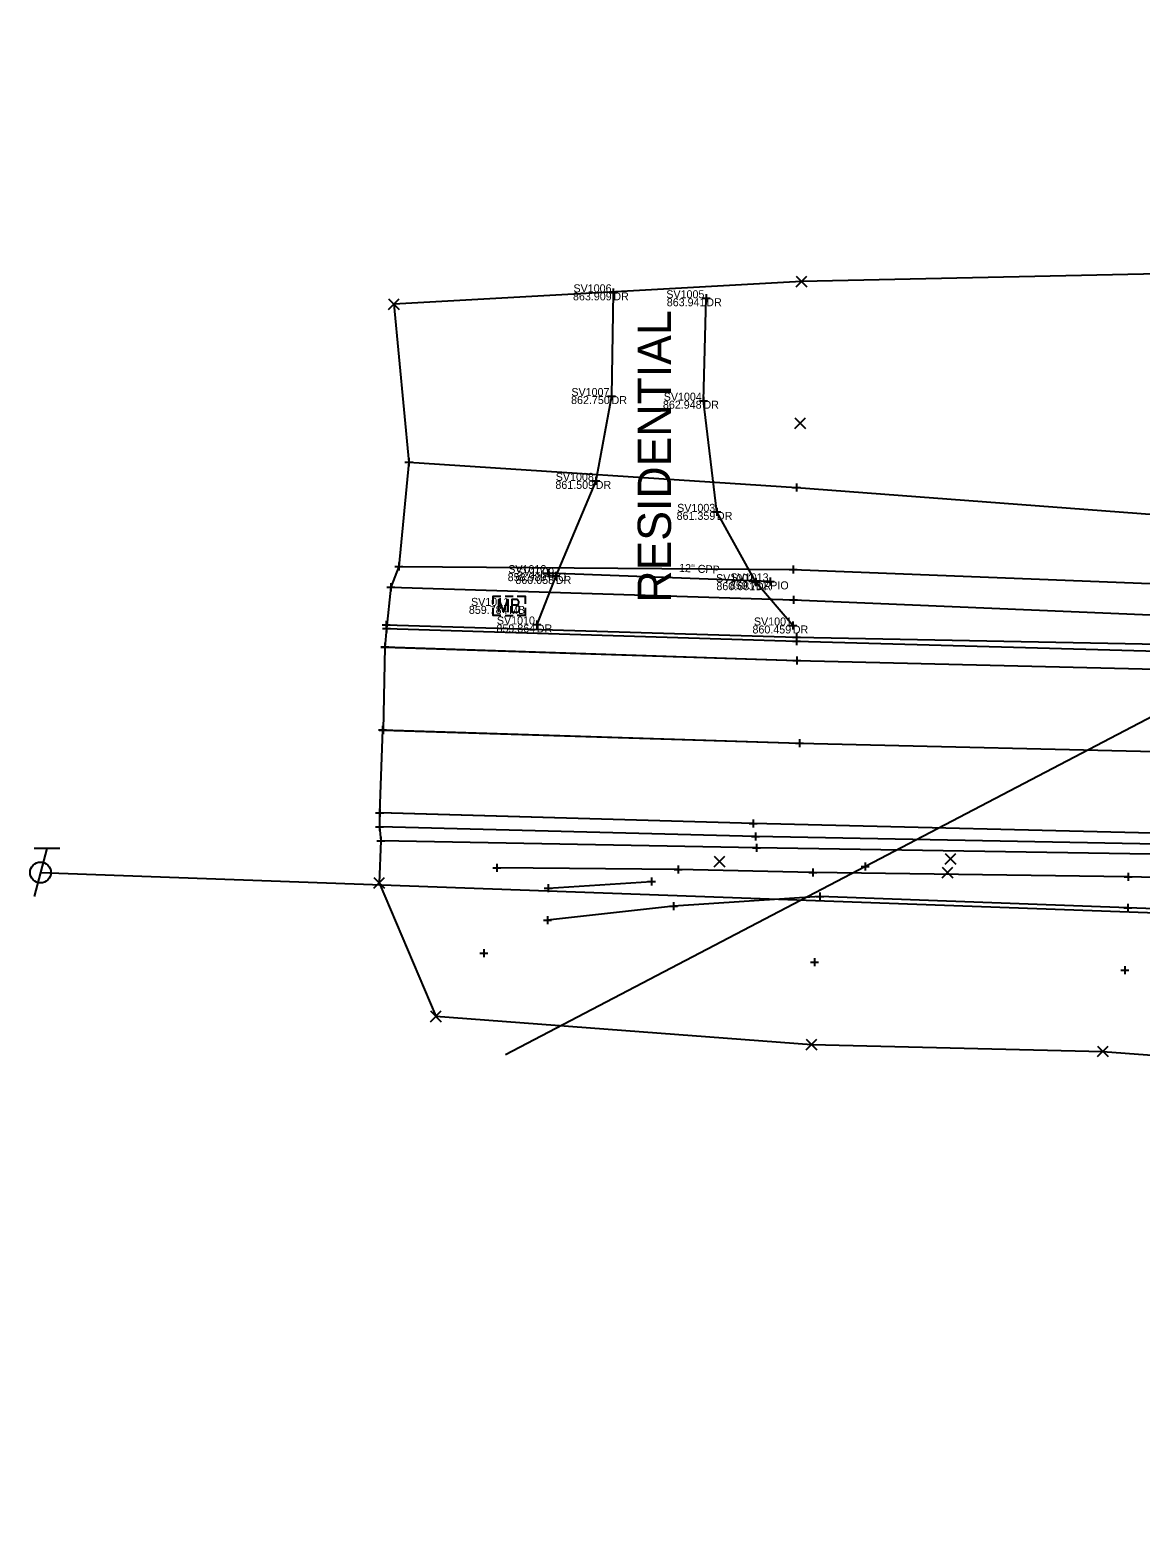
# Model space of a CAD drawing. Extents: x 2005176 to 2005823, y 572472 to 572942.
# Drawn here: x 2005176.4 to 2005315.2, y 572515.6 to 572703.5 of the extents above; entities that cross this region are included whole.
import ezdxf

# ---------------------------------------------------------------- set-up
doc = ezdxf.new("R2010")
doc.units = 0
for name, color, linetype in [('_CIVIL_CONSTRUCTION', 7, 'Continuous'), ('DR_X_Storm_Sewer', 7, 'Continuous'), ('DR_X_Text', 7, 'Continuous'), ('DV_X_Property_Line', 7, 'Continuous'), ('GE_X_Alignment_100_Bearings', 7, 'Continuous'), ('GE_X_Alignment_100_Cardinal_Points', 7, 'Continuous'), ('GE_X_Alignment_100_Curve_Data', 7, 'Continuous'), ('GE_X_Alignment_100_Distances', 7, 'Continuous'), ('GE_X_Alignment_100_Stations', 7, 'Continuous'), ('GE_X_Alignment_500_Bearings', 7, 'Continuous'), ('GE_X_Alignment_500_Cardinal_Points', 7, 'Continuous'), ('GE_X_Alignment_500_Distances', 7, 'Continuous'), ('PV_X_COP', 7, 'Continuous'), ('SC_Scratch1', 7, 'Continuous'), ('SC_Scratch10', 7, 'Continuous'), ('SC_Scratch8', 7, 'Continuous'), ('SV_P_Mon_Cells_Set', 7, 'Continuous'), ('SV_X_Control_Cells_Found', 7, 'Continuous'), ('SV_X_Mon_Cells_Found', 7, 'Continuous'), ('SV_X_Random_Point', 7, 'Continuous'), ('SV_X_Terrain_Boundary', 7, 'Continuous'), ('UT_X_Overhead_Electric', 7, 'Continuous'), ('UT_X_Overhead_Telecom', 7, 'Continuous')]:
    doc.layers.add(name, color=color, linetype=linetype)

msp = doc.modelspace()

# ---------------------------------------------------------------- linework, layer by layer
at = {"layer": '_CIVIL_CONSTRUCTION'}
for p, q in [((2005240.59, 572635.62), (2005241.59, 572635.62)), ((2005241.09, 572636.12), (2005241.09, 572635.12)), ((2005241.09, 572635.62), (2005241.09, 572635.62)), ((2005268.86, 572635.09), (2005268.86, 572634.09)), ((2005268.36, 572634.59), (2005269.36, 572634.59)), ((2005268.86, 572634.59), (2005268.86, 572634.59))]:
    msp.add_line(p, q, dxfattribs=at)
at = {"layer": 'DR_X_Storm_Sewer'}
msp.add_line((2005268.86, 572634.59), (2005241.09, 572635.62), dxfattribs=at)
at = {"layer": 'GE_X_Alignment_100_Bearings'}
for points in [[(2005220.7, 572626.42), (2005272.19, 572624.71), (2005322.24, 572623.5), (2005370.59, 572622.7), (2005425.14, 572621.65), (2005477.36, 572620.84), (2005525.07, 572619.6), (2005576.7, 572617.86), (2005628.14, 572615.99), (2005678.39, 572614.09), (2005728.23, 572612.03), (2005777.04, 572611.02), (2005819.95, 572609.99)], [(2005818.64, 572588.97), (2005775.2, 572590.4), (2005728.29, 572591.88), (2005676.68, 572593.61), (2005626.55, 572595.19), (2005577.83, 572596.72), (2005526.97, 572598.44), (2005477.01, 572599.53), (2005423.67, 572600.7), (2005368.75, 572601.99), (2005321.74, 572602.99), (2005266.72, 572604.35), (2005220.03, 572605.66)]]:
    msp.add_lwpolyline(points, dxfattribs=at)
at = {"layer": 'GE_X_Alignment_100_Cardinal_Points'}
msp.add_lwpolyline([(2005220.5, 572615.99), (2005272.51, 572614.37), (2005322.2, 572613.2), (2005370.62, 572612.29), (2005424.94, 572611.27), (2005476.5, 572610.17), (2005524.32, 572608.79), (2005576.49, 572607.4), (2005627.69, 572605.77), (2005677.11, 572603.68), (2005728.03, 572601.92), (2005776.18, 572600.5), (2005820.14, 572599.28)], dxfattribs=at)
at = {"layer": 'GE_X_Alignment_100_Curve_Data'}
for points in [[(2005249.25, 572670.71), (2005249.03, 572657.75), (2005247.05, 572647.15), (2005242.07, 572635.27), (2005239.68, 572629.21)], [(2005271.68, 572629.08), (2005267.07, 572634.49), (2005262.2, 572643.28), (2005260.51, 572657.17), (2005260.87, 572669.97)]]:
    msp.add_lwpolyline(points, dxfattribs=at)
at = {"layer": 'GE_X_Alignment_100_Distances'}
for points in [[(2005220.68, 572626.38), (2005272.19, 572624.71), (2005322.24, 572623.5), (2005370.59, 572622.7), (2005425.14, 572621.65), (2005477.36, 572620.84), (2005525.07, 572619.6), (2005576.7, 572617.86), (2005628.14, 572615.99), (2005678.39, 572614.09), (2005728.23, 572612.03), (2005777.04, 572611.02), (2005820.02, 572609.9)], [(2005818.7, 572589.05), (2005775.2, 572590.4), (2005728.29, 572591.88), (2005676.68, 572593.61), (2005626.55, 572595.19), (2005577.83, 572596.72), (2005526.97, 572598.44), (2005477.01, 572599.53), (2005423.67, 572600.7), (2005368.75, 572601.99), (2005321.74, 572602.99), (2005266.72, 572604.35), (2005220.06, 572605.65)]]:
    msp.add_lwpolyline(points, dxfattribs=at)
at = {"layer": 'GE_X_Alignment_100_Stations'}
for points in [[(2005222.43, 572636.47), (2005271.73, 572636.06), (2005321.63, 572634.11), (2005368.05, 572633.72), (2005426.44, 572630.35), (2005456.6, 572629.27), (2005476.49, 572629.52), (2005493.02, 572629.48), (2005502.46, 572637.33)], [(2005435.44, 572594.97), (2005419.01, 572594.84), (2005363.8, 572596.44), (2005313.6, 572597.65), (2005274.17, 572598.2), (2005257.36, 572598.58), (2005234.71, 572598.81)]]:
    msp.add_lwpolyline(points, dxfattribs=at)
at = {"layer": 'GE_X_Alignment_500_Bearings'}
for points in [[(2005221.46, 572633.88), (2005271.77, 572632.29), (2005321.33, 572630.21), (2005368.11, 572629.36), (2005426.58, 572628.14), (2005455.88, 572627.02), (2005475.7, 572627.77)], [(2005241.12, 572596.26), (2005254.04, 572597.09)]]:
    msp.add_lwpolyline(points, dxfattribs=at)
at = {"layer": 'GE_X_Alignment_500_Cardinal_Points'}
for points in [[(2005223.7, 572649.48), (2005272.16, 572646.31), (2005321.29, 572642.61), (2005368.45, 572643.7), (2005424.94, 572638.4), (2005464.26, 572637.84), (2005477.31, 572636.75), (2005486.33, 572634.29), (2005489.17, 572649.33), (2005492.03, 572660.48), (2005500.98, 572662.63), (2005517.14, 572685.76), (2005532.69, 572703.48)], [(2005442.09, 572590.88), (2005418.43, 572590.46), (2005365.12, 572591.87), (2005313.53, 572593.79), (2005275.04, 572595.23), (2005256.78, 572594), (2005241.01, 572592.26)]]:
    msp.add_lwpolyline(points, dxfattribs=at)
at = {"layer": 'GE_X_Alignment_500_Distances'}
msp.add_lwpolyline([(2005220.4, 572616.04), (2005272.51, 572614.37), (2005322.2, 572613.2), (2005370.62, 572612.29), (2005424.94, 572611.27), (2005476.5, 572610.17), (2005524.32, 572608.79), (2005576.49, 572607.4), (2005627.69, 572605.77), (2005677.11, 572603.68), (2005728.03, 572601.92), (2005776.18, 572600.5), (2005820.14, 572599.26)], dxfattribs=at)
at = {"layer": 'PV_X_COP'}
for p, q in [((2005235.72, 572632.75), (2005236.72, 572632.75)), ((2005236.23, 572631.53), (2005236.23, 572631.53)), ((2005235.72, 572630.31), (2005236.72, 572630.31))]:
    msp.add_line(p, q, dxfattribs=at)
for points in [[(2005234.23, 572631.78), (2005234.23, 572632.75), (2005235.2, 572632.75)], [(2005237.24, 572632.75), (2005238.23, 572632.75), (2005238.23, 572631.78)], [(2005235.2, 572630.31), (2005234.23, 572630.31), (2005234.23, 572631.28)], [(2005234.94, 572630.73), (2005234.94, 572632.33), (2005235.52, 572630.73), (2005236.07, 572632.33), (2005236.07, 572630.73)], [(2005237.25, 572631.6), (2005237.32, 572631.66), (2005237.36, 572631.7), (2005237.38, 572631.74), (2005237.39, 572631.76), (2005237.42, 572631.81), (2005237.43, 572631.85), (2005237.46, 572631.94), (2005237.46, 572631.98), (2005237.46, 572632.03), (2005237.44, 572632.1), (2005237.42, 572632.17), (2005237.38, 572632.22), (2005237.32, 572632.27), (2005237.27, 572632.29), (2005237.24, 572632.31), (2005237.18, 572632.33), (2005236.56, 572632.33), (2005236.56, 572630.73), (2005237.25, 572630.73), (2005237.34, 572630.78), (2005237.42, 572630.84), (2005237.48, 572630.95), (2005237.52, 572631.06), (2005237.53, 572631.17), (2005237.53, 572631.25), (2005237.51, 572631.32), (2005237.46, 572631.44), (2005237.39, 572631.51), (2005237.25, 572631.6), (2005236.56, 572631.6)], [(2005238.23, 572631.28), (2005238.23, 572630.31), (2005237.24, 572630.31)]]:
    msp.add_lwpolyline(points, dxfattribs=at)
at = {"layer": 'SC_Scratch1'}
for p, q in [((2005180.07, 572601.21), (2005176.87, 572601.21)), ((2005178.47, 572601.21), (2005176.87, 572595.21))]:
    msp.add_line(p, q, dxfattribs=at)
msp.add_circle((2005177.67, 572598.21), 1.3, dxfattribs=at)
at = {"layer": 'SC_Scratch10'}
for points in [[(2005220.88, 572629.15), (2005272.14, 572627.64), (2005321.83, 572626.68), (2005370.65, 572626), (2005424.7, 572625.92), (2005476.69, 572625.33), (2005525.49, 572622.56), (2005576.48, 572620.99), (2005628.3, 572618.68), (2005678.32, 572615.98), (2005728.35, 572614.83)], [(2005445.69, 572596.69), (2005423.63, 572598.01), (2005368.95, 572599.06), (2005321.59, 572600.44), (2005267.14, 572601.3), (2005220.21, 572602.17)]]:
    msp.add_lwpolyline(points, dxfattribs=at)
at = {"layer": 'SC_Scratch8'}
for points in [[(2005220.9, 572628.72), (2005272.16, 572627.13), (2005321.83, 572625.74), (2005370.81, 572625), (2005424.98, 572624.56), (2005477.31, 572623.7), (2005525.21, 572621.63), (2005576.56, 572620.01), (2005628.24, 572617.89), (2005678.25, 572615.23), (2005728.27, 572613.25), (2005777.12, 572612.24), (2005820.02, 572611.5)], [(2005818.66, 572586.64), (2005775.01, 572588.28), (2005728.16, 572589.79), (2005676.75, 572591.58), (2005626.73, 572593.57), (2005577.92, 572595.76), (2005527.42, 572597.32), (2005476.91, 572598.65), (2005423.43, 572599.27), (2005368.77, 572600.6), (2005321.59, 572601.67), (2005267.03, 572602.73), (2005220.03, 572603.93)]]:
    msp.add_lwpolyline(points, dxfattribs=at)
at = {"layer": 'SV_P_Mon_Cells_Set'}
for p, q in [((2005248.75, 572670.71), (2005249.75, 572670.71)), ((2005249.25, 572671.21), (2005249.25, 572670.21)), ((2005249.25, 572670.71), (2005249.25, 572670.71)), ((2005260.87, 572670.47), (2005260.87, 572669.47)), ((2005260.37, 572669.97), (2005261.37, 572669.97)), ((2005260.87, 572669.97), (2005260.87, 572669.97)), ((2005248.53, 572657.75), (2005249.53, 572657.75)), ((2005249.03, 572658.25), (2005249.03, 572657.25)), ((2005249.03, 572657.75), (2005249.03, 572657.75)), ((2005260.01, 572657.17), (2005261.01, 572657.17)), ((2005260.51, 572657.67), (2005260.51, 572656.67)), ((2005260.51, 572657.17), (2005260.51, 572657.17)), ((2005223.7, 572649.98), (2005223.7, 572648.98)), ((2005223.2, 572649.48), (2005224.2, 572649.48)), ((2005223.7, 572649.48), (2005223.7, 572649.48)), ((2005246.55, 572647.15), (2005247.55, 572647.15)), ((2005247.05, 572647.65), (2005247.05, 572646.65)), ((2005247.05, 572647.15), (2005247.05, 572647.15)), ((2005271.66, 572646.31), (2005272.66, 572646.31)), ((2005272.16, 572646.81), (2005272.16, 572645.81)), ((2005272.16, 572646.31), (2005272.16, 572646.31)), ((2005261.7, 572643.28), (2005262.7, 572643.28)), ((2005262.2, 572643.78), (2005262.2, 572642.78)), ((2005262.2, 572643.28), (2005262.2, 572643.28)), ((2005222.43, 572636.97), (2005222.43, 572635.97)), ((2005271.73, 572636.56), (2005271.73, 572635.56)), ((2005221.93, 572636.47), (2005222.93, 572636.47)), ((2005222.43, 572636.47), (2005222.43, 572636.47)), ((2005241.57, 572635.27), (2005242.57, 572635.27)), ((2005242.07, 572635.77), (2005242.07, 572634.77)), ((2005242.07, 572635.27), (2005242.07, 572635.27)), ((2005267.07, 572634.99), (2005267.07, 572633.99)), ((2005271.23, 572636.06), (2005272.23, 572636.06)), ((2005271.73, 572636.06), (2005271.73, 572636.06)), ((2005220.96, 572633.88), (2005221.96, 572633.88)), ((2005221.46, 572634.38), (2005221.46, 572633.38)), ((2005221.46, 572633.88), (2005221.46, 572633.88)), ((2005266.57, 572634.49), (2005267.57, 572634.49)), ((2005267.07, 572634.49), (2005267.07, 572634.49)), ((2005271.77, 572632.79), (2005271.77, 572631.79)), ((2005271.27, 572632.29), (2005272.27, 572632.29)), ((2005271.77, 572632.29), (2005271.77, 572632.29)), ((2005220.38, 572629.15), (2005221.38, 572629.15)), ((2005220.88, 572629.65), (2005220.88, 572628.65)), ((2005220.88, 572629.15), (2005220.88, 572629.15)), ((2005220.9, 572629.22), (2005220.9, 572628.22)), ((2005239.18, 572629.21), (2005240.18, 572629.21)), ((2005239.68, 572629.71), (2005239.68, 572628.71)), ((2005239.68, 572629.21), (2005239.68, 572629.21)), ((2005271.18, 572629.08), (2005272.18, 572629.08)), ((2005271.68, 572629.58), (2005271.68, 572628.58)), ((2005271.68, 572629.08), (2005271.68, 572629.08)), ((2005220.4, 572628.72), (2005221.4, 572628.72)), ((2005220.9, 572628.72), (2005220.9, 572628.72)), ((2005271.64, 572627.64), (2005272.64, 572627.64)), ((2005271.66, 572627.13), (2005272.66, 572627.13)), ((2005272.14, 572628.14), (2005272.14, 572627.14)), ((2005272.14, 572627.64), (2005272.14, 572627.64)), ((2005272.16, 572627.63), (2005272.16, 572626.63)), ((2005272.16, 572627.13), (2005272.16, 572627.13)), ((2005220.18, 572626.38), (2005221.18, 572626.38)), ((2005220.2, 572626.42), (2005221.2, 572626.42)), ((2005220.68, 572626.88), (2005220.68, 572625.88)), ((2005220.68, 572626.38), (2005220.68, 572626.38)), ((2005220.7, 572626.92), (2005220.7, 572625.92)), ((2005220.7, 572626.42), (2005220.7, 572626.42)), ((2005272.19, 572625.21), (2005272.19, 572624.21)), ((2005272.19, 572625.21), (2005272.19, 572624.21)), ((2005271.69, 572624.71), (2005272.69, 572624.71)), ((2005271.69, 572624.71), (2005272.69, 572624.71)), ((2005272.19, 572624.71), (2005272.19, 572624.71)), ((2005272.19, 572624.71), (2005272.19, 572624.71)), ((2005219.9, 572616.04), (2005220.9, 572616.04)), ((2005220, 572615.99), (2005221, 572615.99)), ((2005220.4, 572616.54), (2005220.4, 572615.54)), ((2005220.4, 572616.04), (2005220.4, 572616.04)), ((2005220.5, 572616.49), (2005220.5, 572615.49)), ((2005220.5, 572615.99), (2005220.5, 572615.99)), ((2005272.01, 572614.37), (2005273.01, 572614.37)), ((2005272.01, 572614.37), (2005273.01, 572614.37)), ((2005272.51, 572614.87), (2005272.51, 572613.87)), ((2005272.51, 572614.87), (2005272.51, 572613.87)), ((2005272.51, 572614.37), (2005272.51, 572614.37)), ((2005272.51, 572614.37), (2005272.51, 572614.37)), ((2005219.53, 572605.66), (2005220.53, 572605.66)), ((2005219.56, 572605.65), (2005220.56, 572605.65)), ((2005220.03, 572606.16), (2005220.03, 572605.16)), ((2005220.03, 572605.66), (2005220.03, 572605.66)), ((2005220.06, 572606.15), (2005220.06, 572605.15)), ((2005220.06, 572605.65), (2005220.06, 572605.65)), ((2005266.72, 572604.85), (2005266.72, 572603.85)), ((2005266.72, 572604.85), (2005266.72, 572603.85)), ((2005219.53, 572603.93), (2005220.53, 572603.93)), ((2005220.03, 572604.43), (2005220.03, 572603.43)), ((2005220.03, 572603.93), (2005220.03, 572603.93)), ((2005220.21, 572602.67), (2005220.21, 572601.67)), ((2005266.22, 572604.35), (2005267.22, 572604.35)), ((2005266.22, 572604.35), (2005267.22, 572604.35)), ((2005266.53, 572602.73), (2005267.53, 572602.73)), ((2005266.72, 572604.35), (2005266.72, 572604.35)), ((2005266.72, 572604.35), (2005266.72, 572604.35)), ((2005267.03, 572603.23), (2005267.03, 572602.23)), ((2005267.03, 572602.73), (2005267.03, 572602.73)), ((2005219.71, 572602.17), (2005220.71, 572602.17)), ((2005220.21, 572602.17), (2005220.21, 572602.17)), ((2005266.64, 572601.3), (2005267.64, 572601.3)), ((2005267.14, 572601.8), (2005267.14, 572600.8)), ((2005267.14, 572601.3), (2005267.14, 572601.3)), ((2005234.71, 572599.31), (2005234.71, 572598.31)), ((2005257.36, 572599.08), (2005257.36, 572598.08)), ((2005280.21, 572598.98), (2005281.21, 572598.98)), ((2005280.71, 572599.48), (2005280.71, 572598.48)), ((2005280.71, 572598.98), (2005280.71, 572598.98)), ((2005234.21, 572598.81), (2005235.21, 572598.81)), ((2005234.71, 572598.81), (2005234.71, 572598.81)), ((2005253.54, 572597.09), (2005254.54, 572597.09)), ((2005254.04, 572597.59), (2005254.04, 572596.59)), ((2005254.04, 572597.09), (2005254.04, 572597.09)), ((2005256.86, 572598.58), (2005257.86, 572598.58)), ((2005257.36, 572598.58), (2005257.36, 572598.58)), ((2005273.67, 572598.2), (2005274.67, 572598.2)), ((2005274.17, 572598.7), (2005274.17, 572597.7)), ((2005274.17, 572598.2), (2005274.17, 572598.2)), ((2005313.1, 572597.65), (2005314.1, 572597.65)), ((2005313.6, 572598.15), (2005313.6, 572597.15)), ((2005313.6, 572597.65), (2005313.6, 572597.65)), ((2005240.62, 572596.26), (2005241.62, 572596.26)), ((2005241.12, 572596.76), (2005241.12, 572595.76)), ((2005241.12, 572596.26), (2005241.12, 572596.26)), ((2005274.54, 572595.23), (2005275.54, 572595.23)), ((2005275.04, 572595.73), (2005275.04, 572594.73)), ((2005275.04, 572595.23), (2005275.04, 572595.23)), ((2005256.28, 572594), (2005257.28, 572594)), ((2005256.78, 572594.5), (2005256.78, 572593.5)), ((2005256.78, 572594), (2005256.78, 572594)), ((2005313.03, 572593.79), (2005314.03, 572593.79)), ((2005313.53, 572594.29), (2005313.53, 572593.29)), ((2005313.53, 572593.79), (2005313.53, 572593.79)), ((2005240.51, 572592.26), (2005241.51, 572592.26)), ((2005241.01, 572592.76), (2005241.01, 572591.76)), ((2005241.01, 572592.26), (2005241.01, 572592.26)), ((2005232.58, 572588.15), (2005233.58, 572588.15)), ((2005233.08, 572588.65), (2005233.08, 572587.65)), ((2005233.08, 572588.15), (2005233.08, 572588.15)), ((2005273.9, 572587.02), (2005274.9, 572587.02)), ((2005274.4, 572587.52), (2005274.4, 572586.52)), ((2005274.4, 572587.02), (2005274.4, 572587.02)), ((2005312.67, 572585.99), (2005313.67, 572585.99)), ((2005313.17, 572586.49), (2005313.17, 572585.49)), ((2005313.17, 572585.99), (2005313.17, 572585.99))]:
    msp.add_line(p, q, dxfattribs=at)
at = {"layer": 'SV_X_Random_Point'}
for p, q in [((2005272.11, 572671.39), (2005273.44, 572672.72)), ((2005272.11, 572672.72), (2005273.44, 572671.39)), ((2005221.14, 572668.58), (2005222.47, 572669.92)), ((2005221.14, 572669.92), (2005222.47, 572668.58)), ((2005271.92, 572653.68), (2005273.26, 572655.01)), ((2005271.92, 572655.01), (2005273.26, 572653.68)), ((2005261.84, 572598.92), (2005263.17, 572600.26)), ((2005261.84, 572600.26), (2005263.17, 572598.92)), ((2005290.73, 572599.26), (2005292.06, 572600.6)), ((2005290.73, 572600.6), (2005292.06, 572599.26)), ((2005219.31, 572596.24), (2005220.64, 572597.57)), ((2005219.31, 572597.57), (2005220.64, 572596.24)), ((2005290.34, 572597.55), (2005291.67, 572598.88)), ((2005290.34, 572598.88), (2005291.67, 572597.55)), ((2005226.4, 572579.57), (2005227.73, 572580.91)), ((2005226.4, 572580.91), (2005227.73, 572579.57)), ((2005273.36, 572576.06), (2005274.69, 572577.4)), ((2005273.36, 572577.4), (2005274.69, 572576.06)), ((2005309.76, 572575.2), (2005311.09, 572576.53)), ((2005309.76, 572576.53), (2005311.09, 572575.2))]:
    msp.add_line(p, q, dxfattribs=at)
at = {"layer": 'SV_X_Terrain_Boundary'}
for points in [[(2005481.51, 572691.94), (2005424.05, 572668.06), (2005366.51, 572674.15), (2005321.34, 572673.09), (2005272.77, 572672.06), (2005221.81, 572669.25), (2005223.7, 572649.48), (2005222.43, 572636.47), (2005221.46, 572633.88), (2005220.9, 572628.72), (2005220.68, 572626.38), (2005220.5, 572615.99), (2005220.5, 572615.99), (2005220.4, 572616.04), (2005220.03, 572605.66), (2005220.03, 572603.93), (2005220.21, 572602.17), (2005219.97, 572596.9)], [(2005219.97, 572596.9), (2005227.07, 572580.24), (2005274.02, 572576.73), (2005310.42, 572575.86), (2005364.57, 572571.81), (2005414.7, 572571.99), (2005458.48, 572515.56)]]:
    msp.add_lwpolyline(points, dxfattribs=at)
at = {"layer": 'UT_X_Overhead_Electric'}
msp.add_line((2005235.79, 572575.46), (2005462.76, 572694.31), dxfattribs=at)
at = {"layer": 'UT_X_Overhead_Telecom'}
msp.add_line((2005177.67, 572598.21), (2005321.6, 572593.02), dxfattribs=at)

# ---------------------------------------------------------------- texts
at = {"layer": 'DR_X_Text'}
for s, height, rotation, p in [('RESIDENTIAL', 4.1667, 90, (2005256.46, 572631.93)), ('12" CPP', 1, 357.0573, (2005257.44, 572635.8))]:
    msp.add_text(s, height=height, rotation=rotation, dxfattribs=at).set_placement(p)
at = {"layer": 'DV_X_Property_Line'}
for s, p in [('DR', (2005249.25, 572669.71)), ('DR', (2005260.87, 572668.97)), ('DR', (2005249.03, 572656.75)), ('DR', (2005260.51, 572656.17)), ('DR', (2005247.05, 572646.15)), ('DR', (2005262.2, 572642.28)), ('PIO', (2005241.09, 572634.62)), ('DR', (2005242.07, 572634.27)), ('PIO', (2005268.86, 572633.59)), ('DR', (2005267.07, 572633.49)), ('MB', (2005236.23, 572630.53)), ('DR', (2005239.68, 572628.21)), ('DR', (2005271.68, 572628.08))]:
    msp.add_text(s, height=1, dxfattribs=at).set_placement(p)
at = {"layer": 'SV_X_Control_Cells_Found'}
for s, p in [('SV1006', (2005244.27, 572670.71)), ('SV1005', (2005255.87, 572669.97)), ('SV1007', (2005244.01, 572657.75)), ('SV1004', (2005255.55, 572657.17)), ('SV1008', (2005242.06, 572647.15)), ('SV1003', (2005257.23, 572643.28)), ('SV1012', (2005236.12, 572635.62)), ('SV1009', (2005237.11, 572635.27)), ('SV1002', (2005262.09, 572634.49)), ('SV1013', (2005263.89, 572634.59)), ('SV1011', (2005231.47, 572631.53)), ('SV1010', (2005234.7, 572629.21)), ('SV1001', (2005266.82, 572629.08))]:
    msp.add_text(s, height=1, dxfattribs=at).set_placement(p)
at = {"layer": 'SV_X_Mon_Cells_Found'}
for s, p in [('863.909', (2005244.21, 572669.71)), ('863.941', (2005255.93, 572668.97)), ('862.750', (2005243.97, 572656.75)), ('862.948', (2005255.45, 572656.17)), ('861.509', (2005242.01, 572646.15)), ('861.359', (2005257.16, 572642.28)), ('858.989', (2005236.05, 572634.62)), ('860.058', (2005237.01, 572634.27)), ('859.712', (2005263.81, 572633.59)), ('860.681', (2005262.13, 572633.49)), ('859.784', (2005231.2, 572630.53)), ('859.864', (2005234.65, 572628.21)), ('860.459', (2005266.64, 572628.08))]:
    msp.add_text(s, height=1, dxfattribs=at).set_placement(p)

doc.saveas('drawing.dxf')
